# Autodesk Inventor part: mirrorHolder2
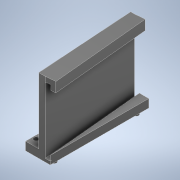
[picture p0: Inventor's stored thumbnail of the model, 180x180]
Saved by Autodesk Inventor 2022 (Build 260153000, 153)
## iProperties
Created: 2022-11
Part Number: mirrorHolder2
Material: Acetal Resin, Black
Document SubType Name: Modeling
Designer: Wojtus
Density: 1.425 g/cm^3
Appearance: Smooth - Black
Author: Wojtus
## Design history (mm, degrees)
sketch "Sketch1"
  geometry: L1 (7.5, -30)-(-7.5, -30); L2 (-7.5, -30)-(-7.5, 30); L3 (-7.5, 30)-(7.5, 30); L4 (7.5, 30)-(7.5, -30); L5 (7.5, -30)-(-7.5, 30); L6 (-7.5, -30)-(7.5, 30); L7 (1.894, 25.132)-(-5.894, 24.396); L8 (0.368, 26.394)-(-4.632, 25.921); L9 (-4.368, 23.134)-(0.632, 23.606); L10 (1.894, 25.132)-(9.716, 25.132); L11 (1.894, -24.868)-(-5.894, -25.604); L12 (0.368, -23.606)-(-4.632, -24.079); L13 (-4.368, -26.866)-(0.632, -26.394); L14 (1.894, -24.868)-(9.716, -24.868); L15 (-4.5, -25.473)-(5.456, -24.532); L16 (-4.5, 24.527)-(5.456, 25.468); C1 r 1.5 at (5.456, 25.468); C2 r 1.5 at (5.456, -24.532); A1 r 1.4 centre (0.5, 25) between (0.632, 23.606) and (0.368, 26.394); A2 r 1.4 centre (-4.5, 24.527) between (-4.632, 25.921) and (-4.368, 23.134); A3 r 1.4 centre (0.5, -25) between (0.632, -26.394) and (0.368, -23.606); A4 r 1.4 centre (-4.5, -25.473) between (-4.632, -24.079) and (-4.368, -26.866); 3 further points
  constraints: 36 end point, 12 point on circle, 8 tangent, 6 centre point, 6 point on line, 4 midpoint, 4 parallel, 3 horizontal, 2 coincident, 2 equal length, 1 perpendicular
  dimensions: "d0" = 15 distance of L2.end L3.end; "d1" = 60 distance between parallel lines of L1 L3; "d2" = 174.6 deg angle of L7 L10; "d3" = 2.8 diameter of A2 (computed from d14); "d4" = 174.6 deg angle of L11 L14; "d5" = 2.8 diameter of A4 (= d3); "d6" = 50 distance of A1.centre A3.centre; "d7" = 7 distance from line of L4 A3.centre; "d8" = 7 distance from line of L4 A1.centre; "d9" = 5 horizontal distance of L9.start L9.end; "d10" = 5 horizontal distance of L13.start L13.end; "d11" = 5 distance from line of L3 A1.centre; "d12" = 10 distance of L15.start L15.end; "d13" = 10 distance of L16.start L16.end; "d14" = 3 diameter of C1; "d15" = 3 diameter of C2
extrude "Extrusion1" new body sketch "Sketch1" distance "d16" = 5; taper "d17" = 0 deg
extrude "Extrusion2" join sketch "Sketch1" distance "d18" = 2.5; taper "d19" = 0 deg
sketch "Sketch2"
  geometry: L1 (7.5, -30)-(7.5, 30) reference; L2 (7.5, -30)-(1.828, 30); L3 (7.5, 30)-(-7.5, 30) reference; L4 (1.828, 30)-(-1.185, 30); L5 (-1.185, 30)-(4.487, -30); L6 (-7.5, -30)-(7.5, -30) reference; L7 (4.487, -30)-(7.5, -30); 2 further points
  constraints: 8 end point, 2 parallel, 1 horizontal, 1 point on line
  dimensions: "d20" = 5.4 deg angle of L2 L1; "d21" = 3 distance between parallel lines of L5 L2
extrude "Extrusion3" cut sketch "Sketch2" distance "d22" = 3; taper "d23" = 0 deg
sketch "Sketch3"
  geometry: L1 (-7.5, -30)-(7.5, -30) reference; L2 (3.559, -30)-(0.559, -30); L3 (0.559, -30)-(-3.499, 30); L4 (1.828, 30)-(7.5, -30) reference; L5 (-1.185, 30)-(1.828, 30) reference; L6 (4.487, -30)-(-1.185, 30) reference; L7 (7.5, -30)-(4.487, -30) reference; L8 (-3.499, 30)-(-1.185, 30); L9 (7.5, 30)-(-7.5, 30) reference; L10 (-1.185, 30)-(4.487, -30); 2 further points
  constraints: 8 end point, 2 point on line, 1 collinear
  dimensions: "d24" = 3 distance of L2.start L2.end
extrude "Extrusion4" join sketch "Sketch3" distance "d25" = 40.2; taper "d26" = 0 deg
sketch "Sketch4"
  geometry: L1 (0, 43.2)-(60.267, 43.2) reference; L2 (0, 43.2)-(60.267, 43.2); L3 (60.267, 43.2)-(60.267, 37.2); L4 (60.267, 37.2)-(0, 37.2); L5 (0, 37.2)-(0, 43.2); L6 (60.267, 43.2)-(60.267, 0) reference; 2 further points
  constraints: 8 end point, 2 parallel, 1 horizontal, 1 perpendicular
  dimensions: "d27" = 6 distance of L2.end L3.end; "d34" = 0 distance between parallel lines of L6 L3
extrude "Extrusion5" join sketch "Sketch4" distance "d28" = 6; taper "d29" = 0 deg
sketch "Sketch5"
  geometry: L1 (0, 0)-(6, 0) reference; L2 (0, 0)-(3, 0); L3 (3, 0)-(3, 3); L4 (3, 3)-(0, 3); L5 (0, 3)-(0, 0); 2 further points
  constraints: 8 end point, 2 parallel, 1 horizontal, 1 perpendicular
  dimensions: "d30" = 3 distance of L4.end L3.end; "d31" = 3 distance of L3.end L2.end
extrude "Extrusion6" cut sketch "Sketch5" extent not by distance; stored distance "d32" = 0; taper "d33" = 0 deg
body "Solid1"
node "Projected Loop1"
